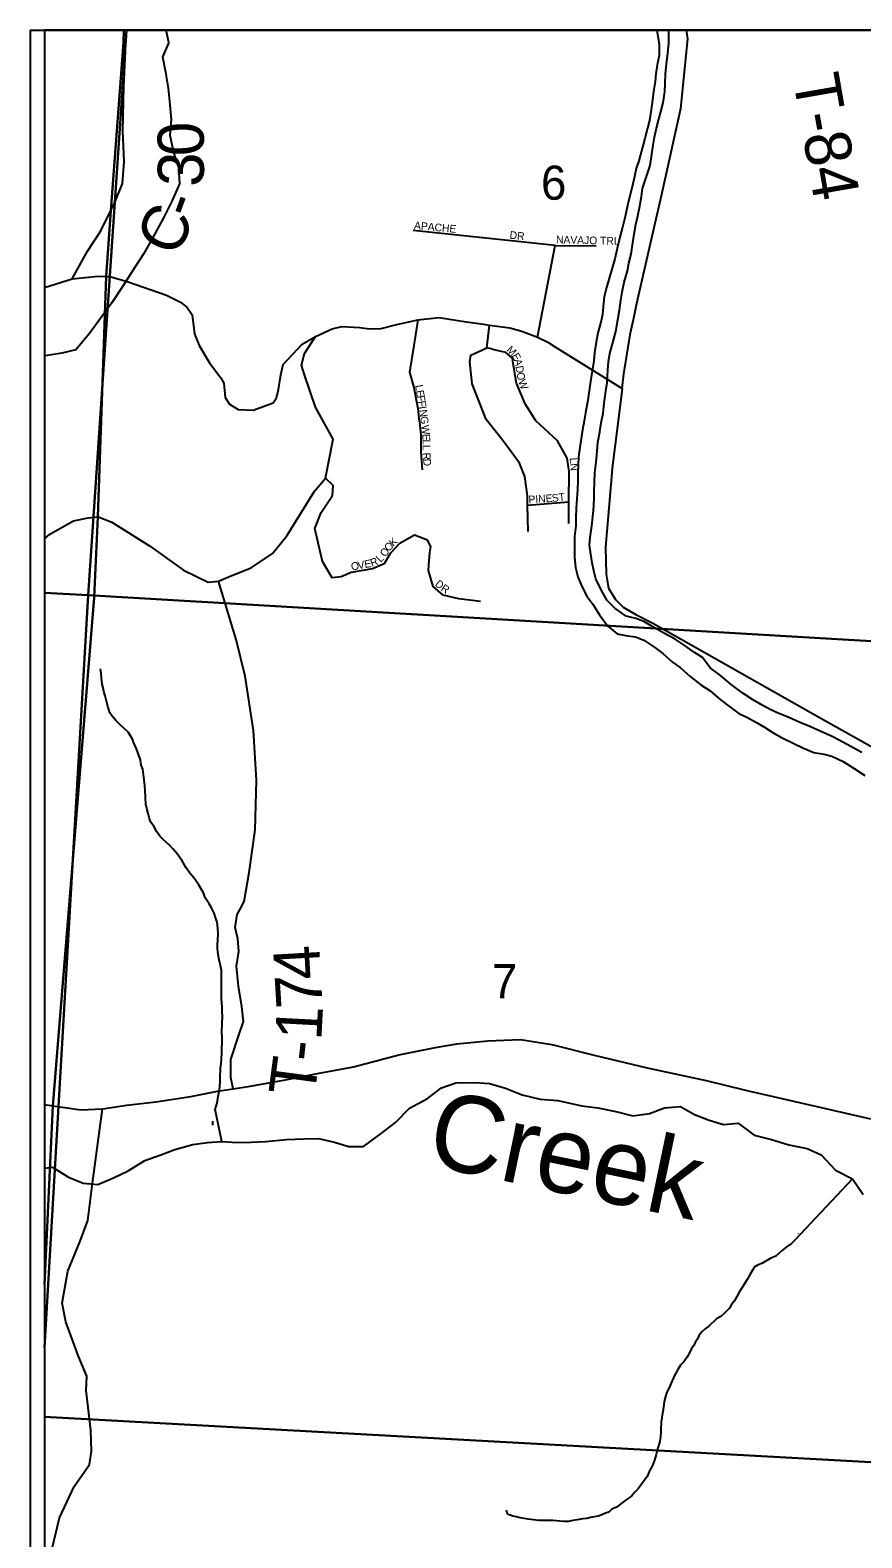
# Model space of a CAD drawing. Extents: x 0 to 34, y 0 to 22.
# Drawn here: x 2.6 to 3.623, y 19.045 to 20.9 of the extents above; entities that cross this region are included whole.
import ezdxf

# ---------------------------------------------------------------- set-up
doc = ezdxf.new("R2010")
doc.units = 0
for name, color, linetype in [('GM_X_County', 7, 'Continuous'), ('GM_X_County_Road', 7, 'Continuous'), ('GM_X_County_Road_Text', 7, 'Continuous'), ('GM_X_Major_River', 7, 'Continuous'), ('GM_X_Minor_River', 7, 'Continuous'), ('GM_X_Minor_River_Text', 7, 'Continuous'), ('GM_X_Section', 7, 'Continuous'), ('GM_X_Section_Text', 7, 'Continuous'), ('GM_X_State_Route', 7, 'Continuous'), ('GM_X_Township', 7, 'Continuous'), ('GM_X_Township_Road', 7, 'Continuous'), ('GM_X_Township_Road_Text', 7, 'Continuous'), ('GM_X_Township_ROW', 7, 'Continuous'), ('GM_X_Township_Subdivision', 7, 'Continuous'), ('GM_X_Township_Subdivision_Text', 7, 'Continuous'), ('SH_Data', 7, 'Continuous')]:
    doc.layers.add(name, color=color, linetype=linetype)

msp = doc.modelspace()

# ---------------------------------------------------------------- linework, layer by layer
at = {"layer": 'GM_X_County'}
msp.add_lwpolyline([(9.4175, 16.6203), (9.4175, 20.9), (2.6175, 20.9), (2.6175, 15.1694)], dxfattribs=at)
at = {"layer": 'GM_X_County_Road'}
for points in [[(2.6515, 20.5939), (2.6707, 20.6281), (2.687, 20.6531), (2.6993, 20.678), (2.7043, 20.6881), (2.7137, 20.7112), (2.7156, 20.7378), (2.714, 20.7757), (2.7153, 20.8304), (2.7175, 20.8831), (2.7187, 20.9)], [(2.6888, 19.5727), (2.7187, 19.5773), (2.7547, 19.5816), (2.7975, 19.5881), (2.8305, 19.5946), (2.8498, 19.5976), (2.8707, 19.6008), (2.9139, 19.6085), (2.9536, 19.6162), (2.9976, 19.6246), (3.0533, 19.6395), (3.0987, 19.6483), (3.1249, 19.653), (3.1628, 19.6565), (3.203, 19.6584), (3.2416, 19.6521), (3.2936, 19.6389), (3.3588, 19.6235), (3.4316, 19.6077), (3.4798, 19.5957), (3.5924, 19.5702), (3.6334, 19.5604)], [(2.6175, 19.5783), (2.6279, 19.5767), (2.6394, 19.575)], [(2.6268, 19.0305), (2.6362, 19.0696), (2.6543, 19.1083), (2.6728, 19.1353), (2.6754, 19.1516), (2.6746, 19.1774), (2.6688, 19.2263), (2.6695, 19.2441), (2.6592, 19.2695), (2.6439, 19.3108), (2.6393, 19.334), (2.6464, 19.3731), (2.6615, 19.4099), (2.6709, 19.4357), (2.6765, 19.4816), (2.6888, 19.5727)], [(2.6394, 19.575), (2.6397, 19.5749), (2.6623, 19.5715), (2.6888, 19.5727)]]:
    msp.add_lwpolyline(points, dxfattribs=at)
at = {"layer": 'GM_X_Major_River'}
for points in [[(3.3708, 20.9), (3.3735, 20.8822)], [(3.3856, 20.8841), (3.3856, 20.9)], [(3.3735, 20.8822), (3.3735, 20.8689), (3.3713, 20.8575), (3.3694, 20.8462), (3.3687, 20.8367), (3.3668, 20.8245), (3.3653, 20.8143), (3.3639, 20.8018), (3.3616, 20.7889), (3.3594, 20.7794), (3.356, 20.7665), (3.3485, 20.7392), (3.3455, 20.7297), (3.3433, 20.7198), (3.3406, 20.7073), (3.3373, 20.6944), (3.3346, 20.6842), (3.332, 20.6709), (3.3287, 20.6576), (3.3249, 20.6436), (3.3219, 20.6315), (3.3189, 20.6186), (3.3155, 20.606), (3.3088, 20.5833), (3.3058, 20.5719), (3.3047, 20.5601), (3.304, 20.5503), (3.3017, 20.5408), (3.2983, 20.5275), (3.2957, 20.5135), (3.2942, 20.5036), (3.2931, 20.493), (3.2913, 20.4809), (3.2894, 20.4706), (3.2857, 20.4448), (3.2831, 20.4293), (3.2812, 20.4194), (3.2794, 20.4084), (3.2764, 20.3895), (3.2745, 20.3751), (3.2738, 20.3648), (3.2734, 20.355), (3.2735, 20.3455), (3.2731, 20.3349), (3.2717, 20.3121), (3.2713, 20.3004), (3.271, 20.2901), (3.2695, 20.2772), (3.2696, 20.2518), (3.2707, 20.2389), (3.2734, 20.2276), (3.2787, 20.2155), (3.2848, 20.2037), (3.292, 20.1939), (3.3004, 20.1806), (3.3103, 20.1666), (3.322, 20.1572), (3.3345, 20.155), (3.3444, 20.1538), (3.3546, 20.1493), (3.3683, 20.1403), (3.3781, 20.1331), (3.3899, 20.1225), (3.3994, 20.1157), (3.4119, 20.1047), (3.4248, 20.0945), (3.4362, 20.087), (3.4487, 20.0764), (3.462, 20.0662), (3.4718, 20.0594), (3.4813, 20.0549), (3.4934, 20.0481), (3.5033, 20.0424), (3.5128, 20.0364), (3.5256, 20.0288), (3.5385, 20.0228), (3.551, 20.0168), (3.5639, 20.0111), (3.5764, 20.0093), (3.5859, 20.0066), (3.5999, 20.0002), (3.6136, 19.9915), (3.6265, 19.9832)], [(3.623, 20.0113), (3.6131, 20.0166), (3.6002, 20.0237), (3.5862, 20.0309), (3.5726, 20.0373), (3.5589, 20.0433), (3.546, 20.0486), (3.5324, 20.0546), (3.5206, 20.0592), (3.5108, 20.0637), (3.5013, 20.069), (3.4884, 20.0765), (3.4767, 20.0844), (3.4623, 20.095), (3.449, 20.106), (3.4365, 20.1154), (3.427, 20.1283), (3.4171, 20.1343), (3.4054, 20.1426), (3.3932, 20.1506), (3.3803, 20.1577), (3.3667, 20.1653), (3.3546, 20.1724), (3.3451, 20.1762), (3.333, 20.1792), (3.3189, 20.1887), (3.3098, 20.1985), (3.3026, 20.2106), (3.2957, 20.225), (3.2931, 20.2348), (3.2912, 20.2447), (3.2896, 20.2553), (3.2881, 20.2663), (3.2888, 20.2758), (3.2907, 20.2902), (3.2929, 20.3091), (3.2936, 20.3235), (3.2936, 20.333), (3.2939, 20.3433), (3.2946, 20.3554), (3.2961, 20.3683), (3.2972, 20.3819), (3.2983, 20.3926), (3.3006, 20.4058), (3.3024, 20.4168), (3.3047, 20.4286), (3.3061, 20.4411), (3.308, 20.4559), (3.3095, 20.4661), (3.3106, 20.4821), (3.3113, 20.4919), (3.3128, 20.5022), (3.3169, 20.517), (3.3203, 20.5291), (3.3229, 20.5435), (3.3248, 20.5553), (3.3266, 20.5678), (3.3281, 20.5776), (3.3307, 20.5898), (3.3345, 20.6038), (3.3363, 20.6133), (3.339, 20.6243), (3.3412, 20.6383), (3.3427, 20.6489), (3.3449, 20.6611), (3.3472, 20.6717), (3.3494, 20.6812), (3.352, 20.6952), (3.3531, 20.7051), (3.3576, 20.7187), (3.3625, 20.7335), (3.3662, 20.7586), (3.3677, 20.7684), (3.3703, 20.7794), (3.3733, 20.7904), (3.376, 20.8011), (3.3786, 20.8105), (3.3804, 20.8242), (3.3808, 20.8344), (3.3815, 20.8458), (3.3826, 20.8587), (3.3841, 20.8712), (3.3856, 20.8841)]]:
    msp.add_lwpolyline(points, dxfattribs=at)
at = {"layer": 'GM_X_Minor_River'}
for points in [[(2.7707, 20.8848), (2.7674, 20.9)], [(2.7707, 20.8848), (2.7629, 20.8672), (2.7666, 20.8482), (2.7696, 20.8285), (2.7719, 20.808), (2.7734, 20.7898), (2.7718, 20.7708), (2.7763, 20.7496), (2.7823, 20.7314), (2.7838, 20.7109), (2.7747, 20.6904), (2.7641, 20.6692), (2.7534, 20.6495), (2.7398, 20.6252), (2.7254, 20.6032), (2.714, 20.585), (2.7003, 20.5646), (2.6874, 20.5464), (2.673, 20.5267), (2.6563, 20.5069), (2.6389, 20.5024), (2.6185, 20.4994), (2.6175, 20.4992)], [(2.835, 19.5345), (2.8357, 19.5328), (2.8277, 19.572), (2.8289, 19.5761), (2.8298, 19.5799), (2.8314, 19.5886), (2.8327, 19.5958), (2.8332, 19.6004), (2.8336, 19.6064), (2.8338, 19.6152), (2.8343, 19.6193), (2.8343, 19.6235), (2.8348, 19.6281), (2.8353, 19.6345), (2.8358, 19.6413), (2.8361, 19.6607), (2.8359, 19.6671), (2.8361, 19.6785), (2.8366, 19.6865), (2.8363, 19.6926), (2.836, 19.6979), (2.8354, 19.7082), (2.8352, 19.7169), (2.8355, 19.734), (2.8353, 19.7431), (2.8343, 19.7492), (2.8325, 19.7564), (2.8311, 19.7629), (2.8305, 19.7701), (2.8306, 19.7751), (2.831, 19.7808), (2.8312, 19.7884), (2.8309, 19.7948), (2.8299, 19.8024), (2.8285, 19.807), (2.8263, 19.8135), (2.823, 19.82), (2.8201, 19.825), (2.8153, 19.8323), (2.8131, 19.8388), (2.8069, 19.8491), (2.8013, 19.8572), (2.7965, 19.863), (2.7917, 19.8695), (2.7869, 19.878), (2.7806, 19.8868), (2.7754, 19.8926), (2.7717, 19.8968), (2.7676, 19.9007), (2.7635, 19.9042), (2.7598, 19.908), (2.7557, 19.9138), (2.7524, 19.9199), (2.7484, 19.9257), (2.7469, 19.9295), (2.7452, 19.9364), (2.7434, 19.9425), (2.7423, 19.9478), (2.7417, 19.9558), (2.7415, 19.9645), (2.7412, 19.9702), (2.7399, 19.9809), (2.7385, 19.9908), (2.7367, 19.9958), (2.7357, 20.0022), (2.7328, 20.0099), (2.7307, 20.016), (2.7288, 20.0202), (2.727, 20.024), (2.7259, 20.0278), (2.7234, 20.0317), (2.7204, 20.0363), (2.7148, 20.0417), (2.71, 20.046), (2.7059, 20.0502), (2.7007, 20.056), (2.6981, 20.0602), (2.6967, 20.064), (2.6956, 20.0678), (2.6942, 20.0728), (2.6924, 20.0812), (2.6906, 20.0865), (2.6899, 20.0907), (2.6885, 20.0953), (2.6882, 20.0991), (2.6879, 20.1037), (2.6872, 20.1086), (2.6866, 20.1143)], [(2.6175, 19.4999), (2.6275, 19.5011), (2.6471, 19.489), (2.6653, 19.4814), (2.6834, 19.4798), (2.7024, 19.4882), (2.7206, 19.4965), (2.741, 19.5094), (2.7607, 19.5162), (2.7781, 19.523), (2.8001, 19.529), (2.8183, 19.5313), (2.8357, 19.5328), (2.8546, 19.5313), (2.872, 19.532), (2.8894, 19.5328), (2.9152, 19.535), (2.9364, 19.5358), (2.9545, 19.5365), (2.9742, 19.532), (2.9916, 19.5266), (3.0098, 19.5266), (3.0318, 19.5425), (3.0492, 19.5562), (3.0666, 19.5736), (3.0886, 19.5857), (3.106, 19.5986), (3.1235, 19.6047), (3.1469, 19.6054), (3.1651, 19.6039), (3.1848, 19.5985), (3.2052, 19.5902), (3.2271, 19.5849), (3.2491, 19.5833), (3.2786, 19.5765), (3.2983, 19.5742), (3.3202, 19.5696), (3.3414, 19.5643), (3.3618, 19.5673), (3.38, 19.5741), (3.3997, 19.5756), (3.4171, 19.5658), (3.4353, 19.5589), (3.4527, 19.5536), (3.4708, 19.5551), (3.4905, 19.5407), (3.5117, 19.5353), (3.5329, 19.5285), (3.5556, 19.5239), (3.573, 19.5163), (3.5903, 19.4974), (3.6115, 19.4867), (3.6244, 19.4677)], [(2.8247, 19.5527), (2.8248, 19.5576)], [(3.6115, 19.4867), (3.54, 19.411), (3.5362, 19.4073), (3.53, 19.4028), (3.5254, 19.3991), (3.5173, 19.3916), (3.5108, 19.3891), (3.4997, 19.3828), (3.4952, 19.381), (3.4906, 19.3781), (3.4886, 19.3743), (3.4855, 19.3694), (3.482, 19.363), (3.4757, 19.3532), (3.4722, 19.3472), (3.4691, 19.342), (3.466, 19.3363), (3.4625, 19.3322), (3.4601, 19.3277), (3.454, 19.3217), (3.4493, 19.3176), (3.444, 19.3147), (3.4347, 19.3057), (3.4301, 19.3024), (3.4255, 19.2983), (3.4224, 19.2938), (3.4204, 19.2893), (3.4177, 19.2855), (3.4161, 19.2817), (3.4134, 19.278), (3.4111, 19.2727), (3.4076, 19.2671), (3.404, 19.2618), (3.3998, 19.2577), (3.3967, 19.2521), (3.392, 19.2442), (3.3868, 19.2317), (3.3825, 19.2231), (3.3813, 19.2189), (3.3797, 19.2129), (3.3784, 19.2026), (3.3776, 19.1985), (3.3762, 19.1879), (3.3757, 19.1788), (3.3756, 19.175), (3.3752, 19.17), (3.3743, 19.1636), (3.3719, 19.1557), (3.3698, 19.1477), (3.3678, 19.1406), (3.3654, 19.1341), (3.3623, 19.1285), (3.3588, 19.1206), (3.3533, 19.1127), (3.3479, 19.1052), (3.3436, 19.1011), (3.3394, 19.0962), (3.3333, 19.0922), (3.3283, 19.0881), (3.3213, 19.0829), (3.3156, 19.0803), (3.3118, 19.0766), (3.3076, 19.0755), (3.303, 19.0733), (3.2992, 19.0719), (3.2935, 19.0708), (3.2893, 19.0701), (3.2847, 19.0687), (3.2798, 19.0684), (3.2726, 19.0674), (3.2676, 19.0663), (3.2623, 19.0653), (3.2559, 19.0654), (3.243, 19.0664), (3.2339, 19.0665), (3.2256, 19.0663), (3.2192, 19.0671), (3.2124, 19.068), (3.2026, 19.0697), (3.198, 19.0709), (3.1935, 19.0718), (3.1871, 19.0741), (3.1857, 19.0791)], [(3.5447, 19.4197), (3.5448, 19.4198)]]:
    msp.add_lwpolyline(points, dxfattribs=at)
at = {"layer": 'GM_X_Section'}
for p, q in [((3.7913, 20.9), (2.7184, 20.9)), ((2.6175, 20.2079), (2.6175, 19.2791)), ((2.6175, 19.2791), (2.6175, 19.1938)), ((2.6175, 19.1938), (2.6175, 18.1627))]:
    msp.add_line(p, q, dxfattribs=at)
for points in [[(2.7184, 20.9), (2.6175, 20.9), (2.6175, 20.2079)], [(2.6175, 20.2079), (2.6713, 20.205), (2.7184, 20.9)], [(2.7184, 20.9), (2.6713, 20.205), (3.7462, 20.1418), (3.7913, 20.9)], [(2.6175, 19.2791), (2.6713, 20.205), (2.6175, 20.2079)], [(2.6175, 19.1938), (3.6864, 19.1354), (3.7462, 20.1418), (2.6713, 20.205), (2.6175, 19.2791)], [(2.6175, 18.1627), (3.6288, 18.1086), (3.6864, 19.1354), (2.6175, 19.1938)]]:
    msp.add_lwpolyline(points, dxfattribs=at)
at = {"layer": 'GM_X_State_Route'}
for points in [[(3.3427, 20.5478), (3.3463, 20.5643), (3.3573, 20.6124), (3.3768, 20.6983), (3.4001, 20.8036), (3.4089, 20.8894), (3.4074, 20.9)], [(2.6175, 20.5833), (2.6515, 20.5939), (2.6678, 20.5958), (2.6838, 20.5973), (2.6933, 20.597), (2.6978, 20.5969), (2.7193, 20.5907), (2.7678, 20.574), (2.7847, 20.5653), (2.7932, 20.5586), (2.7991, 20.5497), (2.8023, 20.5265), (2.8077, 20.512), (2.8205, 20.4908), (2.8344, 20.4723), (2.8381, 20.4657), (2.8399, 20.4479), (2.845, 20.4398), (2.8559, 20.4331), (2.8741, 20.4326), (2.8989, 20.4415), (2.9029, 20.4475), (2.9054, 20.4577), (2.9081, 20.4758), (2.911, 20.4886), (2.9344, 20.5135), (2.9509, 20.5233), (2.9716, 20.5327), (2.9834, 20.5355), (3.0054, 20.5342), (3.0175, 20.5324), (3.0315, 20.5328), (3.051, 20.538), (3.0769, 20.5435), (3.1032, 20.5463), (3.1364, 20.5413), (3.155, 20.5385)], [(3.155, 20.5385), (3.1648, 20.5371), (3.1899, 20.5339), (3.2048, 20.5298), (3.2239, 20.5222), (3.2365, 20.5161), (3.245, 20.511), (3.328, 20.4591)], [(3.328, 20.4591), (3.3302, 20.4771), (3.3382, 20.5277), (3.3427, 20.5478)], [(3.328, 20.4591), (3.3231, 20.4195), (3.3159, 20.361)], [(3.3159, 20.361), (3.3152, 20.3553), (3.3078, 20.264), (3.3085, 20.2306), (3.3115, 20.2135), (3.3199, 20.1996), (3.3295, 20.1903), (3.3449, 20.1812), (3.3659, 20.1705), (3.4291, 20.1348), (3.5717, 20.054), (3.6395, 20.0157)]]:
    msp.add_lwpolyline(points, dxfattribs=at)
at = {"layer": 'GM_X_Township'}
for p, q in [((8.2133, 20.9), (2.7154, 20.9)), ((2.6175, 19.3567), (2.6175, 15.1694))]:
    msp.add_line(p, q, dxfattribs=at)
for points in [[(2.7154, 20.9), (2.6175, 20.9), (2.6175, 19.3567)], [(2.6175, 19.3567), (2.6279, 19.5767), (2.6787, 20.2021), (2.6833, 20.3013), (2.6933, 20.597), (2.6993, 20.678), (2.7146, 20.8847), (2.7154, 20.9)], [(2.7154, 20.9), (2.7146, 20.8847), (2.6993, 20.678), (2.6933, 20.597), (2.6833, 20.3013), (2.6787, 20.2021), (2.6279, 19.5767), (2.6175, 19.3567)]]:
    msp.add_lwpolyline(points, dxfattribs=at)
at = {"layer": 'GM_X_Township_Road'}
for points in [[(2.685, 20.3007), (2.7006, 20.2945), (2.7468, 20.2657), (2.7885, 20.2355), (2.8189, 20.2209), (2.8315, 20.2222), (2.8461, 20.2281), (2.8717, 20.2385), (2.898, 20.256), (2.9156, 20.278), (2.9497, 20.3328), (2.9633, 20.3487), (2.9728, 20.3967), (2.9508, 20.4363), (2.9376, 20.4759), (2.9338, 20.4877), (2.9376, 20.5022), (2.9509, 20.5233)], [(2.6175, 20.2743), (2.6242, 20.2798), (2.6535, 20.2963), (2.6713, 20.3), (2.6833, 20.3013), (2.685, 20.3007)], [(2.8498, 19.5976), (2.8468, 19.6114), (2.8467, 19.6334), (2.8565, 19.6634), (2.8625, 19.6804), (2.8602, 19.6986), (2.8563, 19.7237), (2.8536, 19.7483), (2.8566, 19.7666), (2.8554, 19.7821), (2.852, 19.7958), (2.8546, 19.8121), (2.8582, 19.8186)]]:
    msp.add_lwpolyline(points, dxfattribs=at)
at = {"layer": 'GM_X_Township_ROW'}
msp.add_lwpolyline([(2.8582, 19.8186), (2.8633, 19.828), (2.8695, 19.8638), (2.8769, 19.9161), (2.8782, 19.9771), (2.8745, 20.0382), (2.8645, 20.1054), (2.8533, 20.1503), (2.8315, 20.2222)], dxfattribs=at)
at = {"layer": 'GM_X_Township_Subdivision'}
for points in [[(3.2239, 20.5222), (3.2457, 20.635), (3.2071, 20.6391), (3.071, 20.6535)], [(3.2457, 20.635), (3.296, 20.6345)], [(3.0769, 20.5435), (3.0718, 20.5119), (3.0666, 20.4793), (3.0718, 20.4604), (3.0769, 20.4346), (3.0786, 20.4186)], [(3.1691, 20.5073), (3.1686, 20.5074), (3.1616, 20.509), (3.1648, 20.5371)], [(3.2123, 20.2832), (3.2118, 20.3155), (3.2116, 20.3272), (3.2082, 20.3507), (3.2017, 20.3671), (3.1813, 20.3951), (3.1608, 20.4209), (3.1437, 20.465), (3.1407, 20.4919), (3.1419, 20.5002), (3.1616, 20.509)], [(3.2624, 20.2931), (3.2624, 20.3196), (3.2631, 20.3572), (3.2605, 20.3735), (3.2484, 20.3947), (3.2218, 20.4194), (3.2089, 20.4403), (3.1983, 20.4657), (3.1942, 20.49), (3.1934, 20.4964), (3.1851, 20.5036), (3.1691, 20.5073)], [(3.0786, 20.4186), (3.0787, 20.4183), (3.0804, 20.402), (3.0804, 20.3814), (3.0821, 20.359)], [(3.0903, 20.2419), (3.0916, 20.2572), (3.0927, 20.2648), (3.0885, 20.2724), (3.0726, 20.2788), (3.0537, 20.2681), (3.0427, 20.2563), (3.0352, 20.2434), (3.0211, 20.2373), (2.995, 20.2327), (2.9825, 20.2274), (2.9715, 20.2262), (2.9597, 20.2463), (2.9501, 20.2869), (2.9581, 20.3066), (2.972, 20.3275), (2.9728, 20.3396), (2.9633, 20.3487)], [(3.2118, 20.3155), (3.2624, 20.3196)], [(3.1539, 20.197), (3.1274, 20.2004), (3.108, 20.2049), (3.0955, 20.2155), (3.0898, 20.2352), (3.0903, 20.2418), (3.0903, 20.2419)]]:
    msp.add_lwpolyline(points, dxfattribs=at)
at = {"layer": 'SH_Data'}
for q in [(2.6, 14.1), (9.4, 20.9)]:
    msp.add_line((2.6, 20.9), q, dxfattribs=at)

# ---------------------------------------------------------------- texts
at = {"layer": 'GM_X_County_Road_Text'}
for s, rotation, p in [('0', 91.7572, (2.8142, 20.7459)), ('3', 87.8609, (2.8129, 20.7067)), ('C', 65.6361, (2.7802, 20.619)), ('-', 69.936, (2.8012, 20.6658))]:
    msp.add_text(s, height=0.0568, rotation=rotation, dxfattribs=at).set_placement(p)
at = {"layer": 'GM_X_Minor_River_Text'}
msp.add_text('Creek', height=0.09469, rotation=348.2405, dxfattribs=at).set_placement((3.0849, 19.5046))
at = {"layer": 'GM_X_Section_Text'}
for s, p in [('6', (3.2283, 20.6914)), ('7', (3.1679, 19.709))]:
    msp.add_text(s, height=0.0419, rotation=0, dxfattribs=at).set_placement(p)
at = {"layer": 'GM_X_Township_Road_Text'}
for s, height, rotation, p in [('T-84', 0.05682, 279.9262, (3.5378, 20.8414)), ('4', 0.0568, 93.2386, (2.9577, 19.7332)), ('7', 0.0568, 93.4372, (2.9598, 19.6983)), ('1', 0.0568, 86.9526, (2.958, 19.6563)), ('-', 0.0568, 83.5848, (2.9551, 19.6295)), ('T', 0.0568, 82.4786, (2.9494, 19.5862))]:
    msp.add_text(s, height=height, rotation=rotation, dxfattribs=at).set_placement(p)
at = {"layer": 'GM_X_Township_Subdivision_Text'}
for s, rotation, p in [('APACHE', 354.8977, (3.0718, 20.6552)), ('DR', 353.9905, (3.1893, 20.6435)), ('NAVAJO TRL', 358.6362, (3.2467, 20.6377)), ('M', 316.5844, (3.1851, 20.5058)), ('E', 299.7313, (3.1919, 20.4995)), ('A', 282.805, (3.195, 20.4944)), ('D', 279.3968, (3.1968, 20.4864)), ('O', 279.4494, (3.1982, 20.4782)), ('L', 279.9945, (3.0734, 20.4629)), ('W', 290.531, (3.2, 20.468)), ('E', 279.9676, (3.0745, 20.4563)), ('F', 279.9805, (3.0757, 20.4498)), ('F', 279.8014, (3.0768, 20.4432)), ('I', 278.6448, (3.078, 20.4367)), ('N', 277.5405, (3.0786, 20.4326)), ('G', 277.2321, (3.0797, 20.4244)), ('W', 276.7236, (3.081, 20.4137)), ('E', 272.2409, (3.0823, 20.4031)), ('L', 270.1912, (3.0826, 20.3965)), ('L', 270.5601, (3.0826, 20.3898)), ('R', 273.7762, (3.0828, 20.38)), ('D', 274.2447, (3.0833, 20.3725)), ('LN', 275.7074, (3.2634, 20.3736)), ('ST', 7.125, (3.2422, 20.3194)), ('PINE', 3.6913, (3.2132, 20.3177)), ('K', 43.7673, (3.0468, 20.2641)), ('O', 58.3418, (3.0374, 20.2512)), ('O', 48.9128, (3.0415, 20.2579)), ('O', 10.0463, (2.9955, 20.2352)), ('V', 10.0409, (3.0037, 20.2366)), ('E', 10.0434, (3.0119, 20.2381)), ('R', 19.9547, (3.0202, 20.2397)), ('L', 43.7454, (3.0309, 20.2445)), ('D', 319.5955, (3.097, 20.2173)), ('R', 326.0877, (3.1042, 20.2112))]:
    msp.add_text(s, height=0.00947, rotation=rotation, dxfattribs=at).set_placement(p)

doc.saveas('drawing.dxf')
